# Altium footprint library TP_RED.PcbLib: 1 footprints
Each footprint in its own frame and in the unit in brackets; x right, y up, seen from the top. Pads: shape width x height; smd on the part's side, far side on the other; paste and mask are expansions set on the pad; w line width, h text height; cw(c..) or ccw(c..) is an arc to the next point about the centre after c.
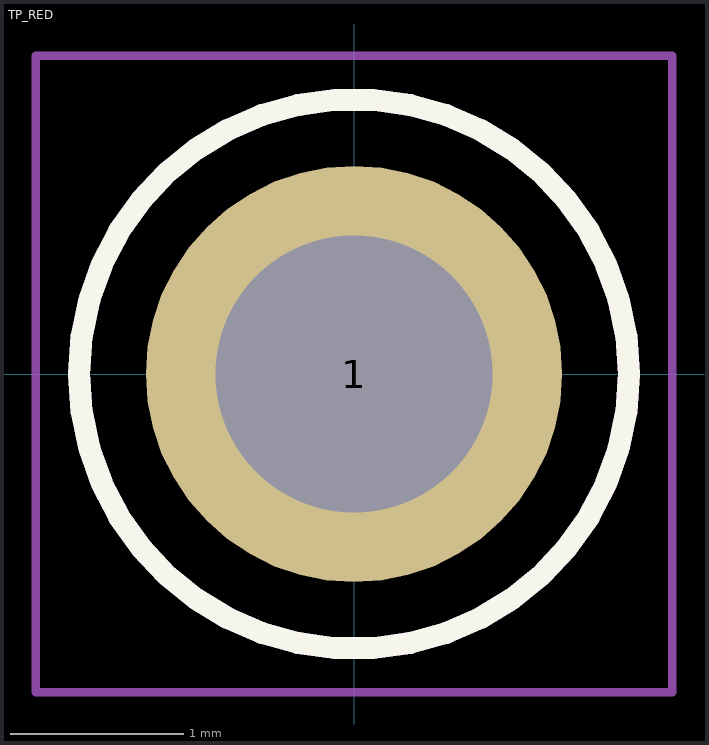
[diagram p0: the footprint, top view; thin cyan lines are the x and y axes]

## TP_RED [mm]
pads (1):
  round 2.4 hole 1.6: 1(0,0)
Top Overlay:
  circle w0.127: c0,0 r1.585
Mechanical 13:
  circle w0.127: c0,0 r1.585
Mechanical 15:
  lines w0.05: -1.835,-1.835 -1.835,1.835 1.835,1.835 1.835,-1.835 -1.835,-1.835
3D body "TP_RED.STEP": height 8.13, standoff -3.56, extent -1.603,-1.607 1.572,1.568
